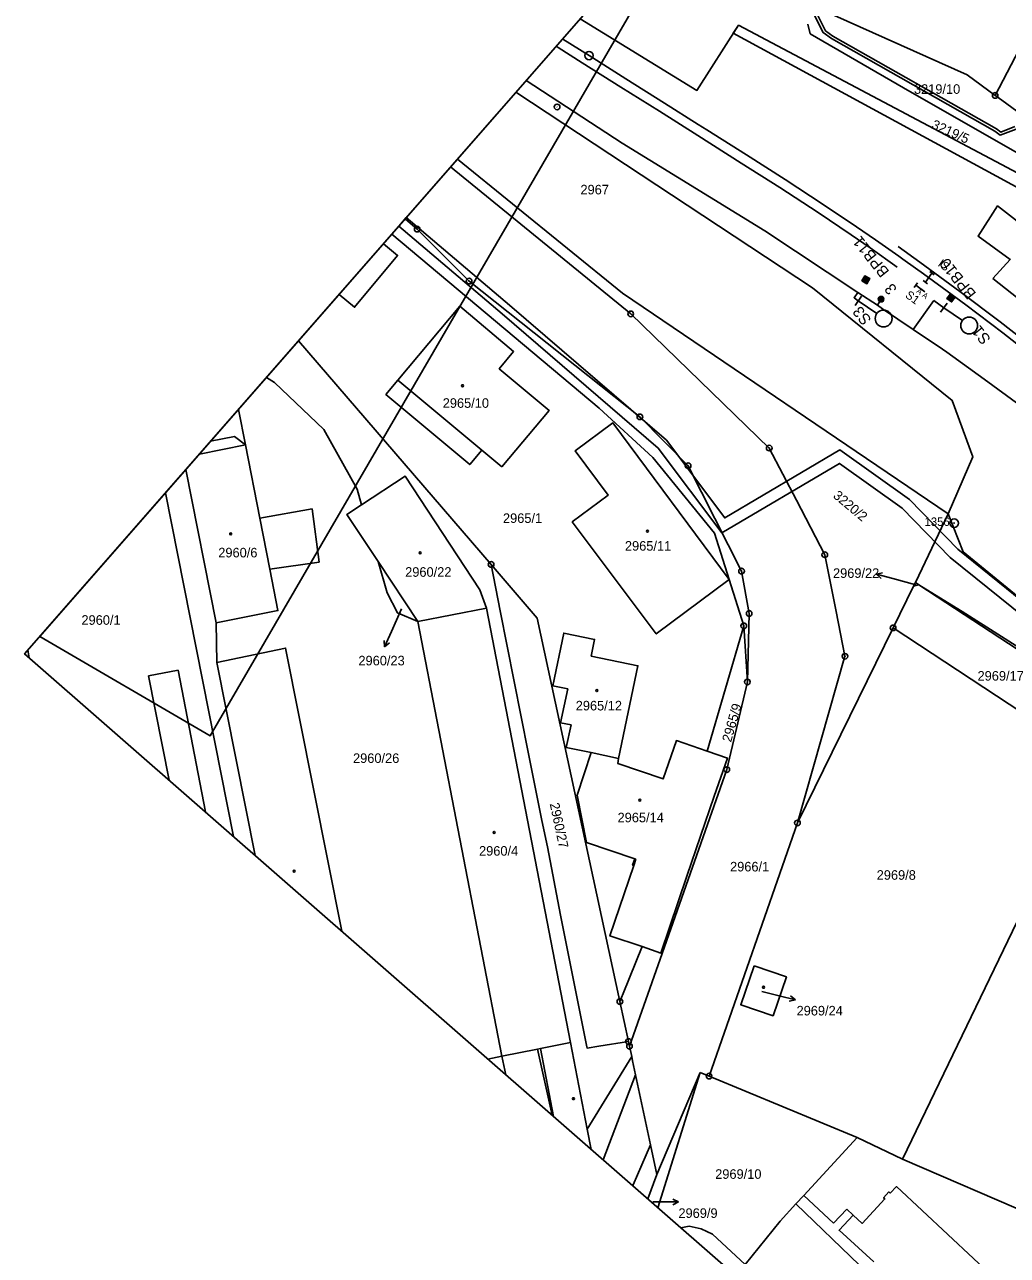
# Model space of a CAD drawing. Extents: x -620475 to -619963, y -1123010 to -1122510.
# Drawn here: x -620474.6 to -620300.1, y -1122840.5 to -1122621.9 of the extents above; entities that cross this region are included whole.
import ezdxf

# ---------------------------------------------------------------- set-up
doc = ezdxf.new("R2010")
doc.units = 0
for name, color, linetype in [('HranDP', 7, 'Continuous'), ('Hranice parcel', 7, 'Continuous'), ('Parcelní čísla', 7, 'Continuous'), ('Pop  PČ popisy', 7, 'Continuous'), ('Rámečky', 7, 'Continuous'), ('Rámečky-tisk', 7, 'Continuous'), ('Vnitřní kresba', 7, 'Continuous'), ('Vrstva 1', 7, 'Continuous'), ('Vrstva 14', 7, 'Continuous'), ('Vrstva 2', 7, 'Continuous'), ('Vrstva 3', 7, 'Continuous'), ('Vrstva 4', 7, 'Continuous'), ('Vrstva 51', 7, 'Continuous'), ('Vrstva 6', 7, 'Continuous'), ('Vrstva 7', 7, 'Continuous'), ('Věcná břemena k části', 7, 'Continuous'), ('Značky bodu BP', 7, 'Continuous'), ('Značky budov', 7, 'Continuous')]:
    doc.layers.add(name, color=color, linetype=linetype)

msp = doc.modelspace()

# ---------------------------------------------------------------- linework, layer by layer
at = {"layer": 'HranDP'}
for points in [[(-620297.09, -1122645.35), (-620318.55, -1122633.1), (-620335.09, -1122623.49), (-620335.54, -1122621.75)], [(-620310.57, -1122708.76), (-620306.2, -1122698.65), (-620309.9, -1122688.62), (-620334.71, -1122668.63), (-620387.37, -1122633.88)], [(-620310.57, -1122708.76), (-620307.94, -1122715.53), (-620278.65, -1122739.48), (-620275.74, -1122741.01)]]:
    msp.add_lwpolyline(points, dxfattribs=at)
at = {"layer": 'Hranice parcel'}
for p, q in [((-620302.25, -1122634.43), (-620294.15, -1122618.83)), ((-620435.41, -1122696.52), (-620436.65, -1122690.22)), ((-620316.42, -1122720.94), (-620310.57, -1122708.76)), ((-620411.83, -1122717.24), (-620404.8, -1122727.88)), ((-620320.37, -1122729), (-620316.74, -1122721.6)), ((-620316.74, -1122721.6), (-620316.42, -1122720.94)), ((-620315.79, -1122721.36), (-620316.74, -1122721.6)), ((-620315.79, -1122721.36), (-620316.42, -1122720.94)), ((-620280.66, -1122744.45), (-620315.79, -1122721.36)), ((-620392.56, -1122725.51), (-620404.8, -1122727.88)), ((-620392.56, -1122725.51), (-620377.65, -1122802.63)), ((-620440.5, -1122735.14), (-620440.62, -1122728.09)), ((-620404.8, -1122727.88), (-620389.89, -1122805.11)), ((-620353.41, -1122750.9), (-620346.9, -1122728.66)), ((-620346.9, -1122728.66), (-620346.26, -1122738.61)), ((-620320.37, -1122729), (-620337.36, -1122763.66)), ((-620284.57, -1122752.56), (-620320.37, -1122729)), ((-620337.36, -1122763.66), (-620328.93, -1122734.05)), ((-620373.99, -1122751.17), (-620369.13, -1122752.19)), ((-620284.57, -1122752.56), (-620318.73, -1122823.4)), ((-620353.06, -1122808.63), (-620337.36, -1122763.66)), ((-620368.9, -1122795.38), (-620367.37, -1122802.49)), ((-620367.19, -1122803.33), (-620367.37, -1122802.49)), ((-620383.51, -1122803.82), (-620389.89, -1122805.11)), ((-620383.51, -1122803.82), (-620383.02, -1122803.72)), ((-620383.02, -1122803.72), (-620377.65, -1122802.63)), ((-620377.65, -1122802.63), (-620374.68, -1122818.03)), ((-620366.79, -1122805.17), (-620367.19, -1122803.33)), ((-620389.89, -1122805.11), (-620392.33, -1122805.6)), ((-620374.68, -1122818.03), (-620366.79, -1122805.17)), ((-620362.33, -1122826.09), (-620354.63, -1122807.98)), ((-620362.14, -1122832), (-620354.63, -1122807.98)), ((-620354.63, -1122807.98), (-620353.06, -1122808.63)), ((-620353.06, -1122808.63), (-620326.76, -1122819.51)), ((-620318.73, -1122823.4), (-620326.76, -1122819.51)), ((-620318.73, -1122823.4), (-620280.92, -1122839.64)), ((-620363.95, -1122830.42), (-620362.33, -1122826.09))]:
    msp.add_line(p, q, dxfattribs=at)
for points in [[(-620296.23, -1122649.3), (-620347.83, -1122621.96), (-620355.23, -1122633.54), (-620375.94, -1122620.82)], [(-620333.59, -1122619.01), (-620307.23, -1122630.79), (-620302.25, -1122634.43)], [(-620297.09, -1122645.35), (-620318.55, -1122633.1), (-620335.09, -1122623.49), (-620335.54, -1122621.75)], [(-620310.57, -1122708.76), (-620306.2, -1122698.65), (-620309.9, -1122688.62), (-620334.71, -1122668.63), (-620387.37, -1122633.88)], [(-620302.25, -1122634.43), (-620301.71, -1122634.83), (-620292.25, -1122641.75)], [(-620342.37, -1122697.07), (-620366.98, -1122673.23), (-620398.96, -1122647.13)], [(-620397.76, -1122645.76), (-620368.46, -1122669.58), (-620310.57, -1122708.76)], [(-620302.66, -1122666.96), (-620267.81, -1122694.49), (-620266.86, -1122693.31), (-620261.82, -1122686.93), (-620261.22, -1122686.17), (-620299.15, -1122656.1), (-620301.83, -1122654.06), (-620305.28, -1122659.46), (-620299.56, -1122663.58), (-620302.66, -1122666.96)], [(-620407.03, -1122656.36), (-620404.9, -1122658.18), (-620395.68, -1122667.41), (-620365.35, -1122691.52), (-620356.78, -1122700.2), (-620347.29, -1122718.92), (-620345.94, -1122726.44), (-620346.26, -1122738.61)], [(-620346.9, -1122728.66), (-620349.5, -1122720.4), (-620352.08, -1122712.18), (-620363.06, -1122698.75), (-620372.55, -1122689.97), (-620409.4, -1122659.07)], [(-620410.89, -1122660.77), (-620408.37, -1122662.86), (-620416.01, -1122672.06), (-620418.76, -1122669.77)], [(-620389.88, -1122700.43), (-620393.43, -1122697.46), (-620395.56, -1122700.01), (-620410.45, -1122687.55), (-620408.32, -1122685), (-620397.34, -1122671.88), (-620387.77, -1122679.92), (-620390.32, -1122682.97), (-620381.44, -1122690.4), (-620389.88, -1122700.43)], [(-620391.77, -1122717.74), (-620425.96, -1122678)], [(-620431.67, -1122684.53), (-620430.21, -1122685.42), (-620421.46, -1122693.76), (-620415.57, -1122704.35), (-620414.76, -1122707.13)], [(-620349.5, -1122720.4), (-620362.45, -1122730.09), (-620377.36, -1122710.19), (-620370.99, -1122705.44), (-620376.85, -1122697.59), (-620370.13, -1122692.59), (-620349.5, -1122720.4)], [(-620443.58, -1122698.14), (-620435.41, -1122696.52)], [(-620440.62, -1122728.09), (-620429.62, -1122725.94), (-620431.07, -1122718.59), (-620432.85, -1122709.54), (-620435.41, -1122696.52)], [(-620328.93, -1122734.05), (-620330.51, -1122726.08), (-620332.51, -1122716.01), (-620337.56, -1122706.31), (-620342.37, -1122697.07)], [(-620440.62, -1122728.09), (-620445.96, -1122700.85)], [(-620414.76, -1122707.13), (-620407.04, -1122702.06), (-620393.75, -1122722.26), (-620392.56, -1122725.51)], [(-620414.76, -1122707.13), (-620417.37, -1122708.84), (-620411.83, -1122717.24)], [(-620310.57, -1122708.76), (-620307.94, -1122715.53), (-620278.65, -1122739.48), (-620275.74, -1122741.01)], [(-620411.83, -1122717.24), (-620410.22, -1122722.77), (-620408.42, -1122726.33), (-620404.8, -1122727.88)], [(-620391.77, -1122717.74), (-620383.57, -1122727.26), (-620368.9, -1122795.38)], [(-620367.37, -1122802.49), (-620372.62, -1122803.29), (-620374.73, -1122803.66), (-620374.83, -1122803.1), (-620379.42, -1122780.06), (-620381.78, -1122767.9), (-620382.73, -1122763.21), (-620385.21, -1122751.08), (-620390.13, -1122725.98), (-620391.77, -1122717.74)], [(-620243.2, -1122764.91), (-620246.23, -1122763.17), (-620280.18, -1122743.84), (-620308.1, -1122726.09), (-620315.79, -1122721.36)], [(-620373.99, -1122751.17), (-620378.41, -1122750.24), (-620377.57, -1122746.24), (-620379.43, -1122745.85), (-620378.17, -1122739.85), (-620380.83, -1122739.29), (-620378.87, -1122729.94), (-620373.38, -1122731.07), (-620373.97, -1122734.01), (-620365.7, -1122735.74), (-620369.13, -1122752.19)], [(-620418.29, -1122782.89), (-620428.27, -1122732.6), (-620440.5, -1122735.14)], [(-620474.07, -1122732.99), (-620473.82, -1122734.31)], [(-620433.66, -1122769.44), (-620440.5, -1122735.14)], [(-620346.26, -1122738.61), (-620349.91, -1122754.18), (-620361.74, -1122787.84), (-620367.19, -1122803.33)], [(-620369.13, -1122752.19), (-620369.27, -1122753.08), (-620361.19, -1122755.84), (-620358.86, -1122749.03), (-620353.41, -1122750.9)], [(-620364.94, -1122785.63), (-620370.66, -1122783.71), (-620366.44, -1122771.24), (-620366.65, -1122771.17), (-620366.25, -1122770.01), (-620374.82, -1122767.12), (-620376.48, -1122758.71), (-620373.99, -1122751.17)], [(-620353.41, -1122750.9), (-620349.8, -1122752.13), (-620352.16, -1122758.92), (-620357, -1122773.13), (-620361.6, -1122786.76), (-620364.94, -1122785.63)], [(-620368.9, -1122795.38), (-620368.33, -1122793.98), (-620364.94, -1122785.63)], [(-620345.02, -1122789.02), (-620339.31, -1122791.01), (-620341.69, -1122797.91), (-620347.42, -1122795.94), (-620345.02, -1122789.02)], [(-620380.95, -1122815.55), (-620383.51, -1122803.82)], [(-620383.02, -1122803.72), (-620380.67, -1122815.79)], [(-620366.1, -1122808.4), (-620366.63, -1122805.92), (-620366.79, -1122805.17)], [(-620371.87, -1122823.49), (-620366.1, -1122808.4)], [(-620366.1, -1122808.4), (-620363.45, -1122820.82), (-620362.33, -1122826.09)], [(-620374.68, -1122818.03), (-620373.98, -1122821.65)], [(-620326.76, -1122819.51), (-620336.22, -1122829.85), (-620337.65, -1122831.34), (-620340.44, -1122834.38), (-620346.62, -1122842.11), (-620352.46, -1122836.69), (-620354.47, -1122835.76), (-620356.61, -1122835.3), (-620358.07, -1122835.57)], [(-620323.82, -1122841.64), (-620329.96, -1122836), (-620327.44, -1122833.35), (-620325.88, -1122834.8), (-620321.83, -1122830.45), (-620322.07, -1122830.23), (-620321.11, -1122829.2), (-620320.88, -1122829.41), (-620319.79, -1122828.24), (-620301.53, -1122845.3)]]:
    msp.add_lwpolyline(points, dxfattribs=at)
at = {"layer": 'Pop  PČ popisy'}
for p, q in [((-620323.34, -1122719.48), (-620322.24, -1122719.26)), ((-620320.44, -1122720.26), (-620323.34, -1122719.48)), ((-620323.34, -1122719.48), (-620322.5, -1122720.23)), ((-620316.31, -1122721.37), (-620320.44, -1122720.26)), ((-620407.69, -1122725.63), (-620409.46, -1122729.64)), ((-620409.46, -1122729.64), (-620410.68, -1122732.38)), ((-620410.68, -1122732.38), (-620410.73, -1122731.26)), ((-620410.68, -1122732.38), (-620409.82, -1122731.67)), ((-620343.66, -1122793.6), (-620340.63, -1122794.37)), ((-620340.63, -1122794.37), (-620337.72, -1122795.1)), ((-620337.72, -1122795.1), (-620338.81, -1122795.34)), ((-620337.72, -1122795.1), (-620338.57, -1122794.37)), ((-620361.5, -1122830.98), (-620363.03, -1122830.98)), ((-620361.5, -1122830.98), (-620358.5, -1122830.98)), ((-620358.5, -1122830.98), (-620359.5, -1122830.48)), ((-620358.5, -1122830.98), (-620359.5, -1122831.48))]:
    msp.add_line(p, q, dxfattribs=at)
at = {"layer": 'Rámečky'}
msp.add_lwpolyline([(-620279.07, -1122510.07), (-620474.61, -1122733.62), (-620158.49, -1123010.14)], dxfattribs=at)
at = {"layer": 'Rámečky-tisk'}
msp.add_line((-620351.12, -1122592.44), (-620471.94, -1122730.56), dxfattribs=at)
for points in [[(-620279.07, -1122510.07), (-620474.61, -1122733.62), (-620158.49, -1123010.14)], [(-620471.94, -1122730.56), (-620441.66, -1122748.16), (-620351.12, -1122592.44)]]:
    msp.add_lwpolyline(points, dxfattribs=at)
at = {"layer": 'Vnitřní kresba'}
for p, q in [((-620393.43, -1122697.46), (-620408.32, -1122685)), ((-620437.36, -1122695.04), (-620441.6, -1122695.87)), ((-620437.36, -1122695.04), (-620435.41, -1122696.52)), ((-620449.62, -1122705.04), (-620437.54, -1122766.05)), ((-620432.85, -1122709.54), (-620423.56, -1122707.88)), ((-620423.56, -1122707.88), (-620422.3, -1122717.35)), ((-620422.3, -1122717.35), (-620431.07, -1122718.59)), ((-620447.35, -1122736.5), (-620452.59, -1122737.55)), ((-620442.49, -1122761.71), (-620447.35, -1122736.5)), ((-620448.97, -1122756.05), (-620452.59, -1122737.55)), ((-620366.44, -1122771.24), (-620366.05, -1122770.08)), ((-620366.25, -1122770.01), (-620366.05, -1122770.08)), ((-620389.89, -1122805.11), (-620389.13, -1122808.4)), ((-620366.52, -1122827.92), (-620363.45, -1122820.82)), ((-620366.59, -1122828.11), (-620366.52, -1122827.92)), ((-620366.52, -1122827.92), (-620366.59, -1122828.11)), ((-620330.98, -1122834.72), (-620336.22, -1122829.85)), ((-620337.65, -1122831.34), (-620326.36, -1122842.19)), ((-620328.61, -1122832.23), (-620330.98, -1122834.72)), ((-620327.44, -1122833.35), (-620328.61, -1122832.23))]:
    msp.add_line(p, q, dxfattribs=at)
at = {"layer": 'Vrstva 1'}
for p, q in [((-620323.17, -1122671.7), (-620326.63, -1122669.41)), ((-620322.52, -1122670.62), (-620323.17, -1122671.7)), ((-620313.16, -1122670.85), (-620316.82, -1122675.99)), ((-620311.36, -1122672.15), (-620313.16, -1122670.85))]:
    msp.add_line(p, q, dxfattribs=at)
for points in [[(-620379.07, -1122624.4), (-620379.01, -1122624.44), (-620374.38, -1122627.36), (-620367.83, -1122631.49), (-620360.99, -1122635.8), (-620354.98, -1122639.59), (-620353.48, -1122640.53), (-620346.44, -1122644.97), (-620339.56, -1122649.37), (-620332.79, -1122653.78), (-620326.85, -1122657.77), (-620323.49, -1122660.07), (-620319.33, -1122663), (-620318.62, -1122663.49), (-620316.38, -1122665.1), (-620314.97, -1122666.12), (-620314.06, -1122666.78), (-620307.46, -1122671.65), (-620300.91, -1122676.61), (-620294.55, -1122681.56)], [(-620326.63, -1122669.41), (-620343.18, -1122658.46), (-620368.5, -1122642.9), (-620385.56, -1122631.81)], [(-620326.57, -1122670.9), (-620327.3, -1122670.38), (-620326.63, -1122669.41)], [(-620316.82, -1122675.99), (-620322.23, -1122672.32), (-620323.17, -1122671.7)], [(-620288.27, -1122699.25), (-620297.82, -1122689.49), (-620304.22, -1122684.86), (-620310.82, -1122680.06), (-620311.61, -1122679.52), (-620316.82, -1122675.99)]]:
    msp.add_lwpolyline(points, dxfattribs=at)
at = {"layer": 'Vrstva 14'}
msp.add_lwpolyline([(-620380.23, -1122625.71), (-620379.87, -1122625.94), (-620375.57, -1122628.64), (-620368.73, -1122632.95), (-620361.89, -1122637.25), (-620355.04, -1122641.55), (-620347.33, -1122646.47), (-620340.48, -1122650.8), (-620333.68, -1122655.25), (-620327.8, -1122659.17), (-620324.47, -1122661.49), (-620319.64, -1122664.92)], dxfattribs=at)
at = {"layer": 'Vrstva 2'}
for p, q in [((-620325.89, -1122667.3), (-620324.54, -1122666.95)), ((-620325.8, -1122667.14), (-620324.7, -1122666.86)), ((-620325.7, -1122666.98), (-620324.86, -1122666.76)), ((-620325.61, -1122666.82), (-620325.02, -1122666.67)), ((-620325.51, -1122666.66), (-620325.18, -1122666.57)), ((-620325.42, -1122666.5), (-620325.34, -1122666.48)), ((-620325.82, -1122667.42), (-620324.55, -1122667.09)), ((-620325.66, -1122667.51), (-620324.64, -1122667.25)), ((-620325.5, -1122667.6), (-620324.74, -1122667.41)), ((-620325.34, -1122667.7), (-620324.83, -1122667.57)), ((-620325.18, -1122667.79), (-620324.92, -1122667.73)), ((-620325.99, -1122670.08), (-620327.14, -1122671.72)), ((-620323.29, -1122673.19), (-620326.57, -1122670.9)), ((-620323.01, -1122670.53), (-620322.12, -1122670.32)), ((-620323.01, -1122670.74), (-620322.04, -1122670.5)), ((-620322.92, -1122670.92), (-620322.03, -1122670.71)), ((-620322.9, -1122670.3), (-620322.33, -1122670.16)), ((-620322.72, -1122671.08), (-620322.14, -1122670.94)), ((-620310.79, -1122671.33), (-620311.93, -1122672.96)), ((-620310.8, -1122670.44), (-620309.42, -1122670.24)), ((-620310.74, -1122670.56), (-620309.44, -1122670.37)), ((-620310.69, -1122670.29), (-620309.57, -1122670.13)), ((-620310.59, -1122670.67), (-620309.55, -1122670.52)), ((-620310.58, -1122670.14), (-620309.72, -1122670.01)), ((-620310.47, -1122669.99), (-620309.87, -1122669.9)), ((-620310.44, -1122670.78), (-620309.66, -1122670.67)), ((-620310.36, -1122669.84), (-620310.02, -1122669.79)), ((-620310.29, -1122670.9), (-620309.78, -1122670.82)), ((-620310.25, -1122669.69), (-620310.16, -1122669.68)), ((-620310.14, -1122671.01), (-620309.89, -1122670.97)), ((-620308.08, -1122674.44), (-620311.36, -1122672.15))]:
    msp.add_line(p, q, dxfattribs=at)
for points in [[(-620325.39, -1122666.45), (-620324.48, -1122666.98), (-620325.02, -1122667.89), (-620325.92, -1122667.35)], [(-620325.39, -1122666.45), (-620324.48, -1122666.98), (-620325.02, -1122667.89), (-620325.92, -1122667.35)], [(-620310.21, -1122669.65), (-620309.37, -1122670.27), (-620310, -1122671.12), (-620310.84, -1122670.49)], [(-620310.21, -1122669.65), (-620309.37, -1122670.27), (-620310, -1122671.12), (-620310.84, -1122670.49)]]:
    msp.add_lwpolyline(points, close=True, dxfattribs=at)
for centre, radius in [((-620322.52, -1122670.62), 0.5), ((-620322.06, -1122674.06), 1.5), ((-620306.86, -1122675.3), 1.5)]:
    msp.add_circle(centre, radius, dxfattribs=at)
at = {"layer": 'Vrstva 3'}
for p, q in [((-620313.47, -1122665.98), (-620314.65, -1122667.59)), ((-620313.87, -1122665.68), (-620313.07, -1122666.27)), ((-620315.06, -1122667.29), (-620314.25, -1122667.88))]:
    msp.add_line(p, q, dxfattribs=at)
at = {"layer": 'Vrstva 4'}
msp.add_lwpolyline([(-620319.33, -1122663), (-620318.62, -1122663.49), (-620316.38, -1122665.1)], dxfattribs=at)
at = {"layer": 'Vrstva 51'}
msp.add_lwpolyline([(-620319.5, -1122661.29), (-620315.63, -1122664.05), (-620308.5, -1122669.28), (-620301.34, -1122674.65), (-620293.26, -1122680.96), (-620288.09, -1122685.04), (-620287.72, -1122684.65), (-620280.59, -1122690.26), (-620273.34, -1122696.07), (-620269.67, -1122699.33)], dxfattribs=at)
at = {"layer": 'Vrstva 6'}
for p, q in [((-620316.04, -1122667.72), (-620316.63, -1122668.53)), ((-620314.74, -1122669.3), (-620316.34, -1122668.13))]:
    msp.add_line(p, q, dxfattribs=at)
at = {"layer": 'Vrstva 7'}
msp.add_line((-620380.09, -1122636.45), (-620380.01, -1122636.5), dxfattribs=at)
for centre, radius in [((-620374.38, -1122627.36), 0.75), ((-620380.05, -1122636.48), 0.5)]:
    msp.add_circle(centre, radius, dxfattribs=at)
at = {"layer": 'Věcná břemena k části'}
msp.add_line((-620406.83, -1122656.13), (-620408.15, -1122657.63), dxfattribs=at)
for points in [[(-620334.39, -1122620.13), (-620332.8, -1122623.28), (-620331.31, -1122624.3), (-620302.28, -1122640.81), (-620301.34, -1122641.49), (-620298.51, -1122640.4)], [(-620298.73, -1122639.94), (-620301.26, -1122640.93), (-620302, -1122640.39), (-620331.05, -1122623.88), (-620332.41, -1122622.94), (-620334.05, -1122619.66)], [(-620408.15, -1122657.63), (-620389.78, -1122673.21), (-620362.07, -1122697.07), (-620350.79, -1122712.11), (-620329.91, -1122699.79), (-620318.75, -1122707.75), (-620310.23, -1122716.49), (-620285.9, -1122736.09), (-620287.87, -1122738.92), (-620280.66, -1122744.45), (-620246.32, -1122763.41), (-620202.66, -1122784.39), (-620201.79, -1122782.59), (-620245.45, -1122761.61), (-620279.7, -1122742.7), (-620285.15, -1122738.52), (-620283.23, -1122735.73), (-620308.89, -1122715.01), (-620317.45, -1122706.23), (-620329.81, -1122697.41), (-620350.27, -1122709.47), (-620360.61, -1122695.69), (-620388.48, -1122671.69), (-620406.83, -1122656.13)]]:
    msp.add_lwpolyline(points, dxfattribs=at)
msp.add_lwpolyline([(-620297.19, -1122651.39), (-620296.23, -1122649.3), (-620347.83, -1122621.96), (-620348.75, -1122623.39)], close=True, dxfattribs=at)
at = {"layer": 'Značky bodu BP'}
for centre, radius in [((-620302.25, -1122634.43), 0.5), ((-620302.25, -1122634.43), 0.0303), ((-620404.9, -1122658.18), 0.5), ((-620404.9, -1122658.18), 0.0303), ((-620395.68, -1122667.41), 0.5), ((-620395.68, -1122667.41), 0.0303), ((-620366.98, -1122673.23), 0.5), ((-620366.98, -1122673.23), 0.0303), ((-620365.35, -1122691.52), 0.5), ((-620365.35, -1122691.52), 0.0303), ((-620342.37, -1122697.07), 0.5), ((-620342.37, -1122697.07), 0.0303), ((-620356.78, -1122700.2), 0.5), ((-620356.78, -1122700.2), 0.0303), ((-620309.54, -1122710.4), 0.75), ((-620309.54, -1122710.4), 0.03), ((-620391.77, -1122717.74), 0.5), ((-620332.51, -1122716.01), 0.5), ((-620332.51, -1122716.01), 0.0303), ((-620391.77, -1122717.74), 0.0303), ((-620347.29, -1122718.92), 0.5), ((-620347.29, -1122718.92), 0.0303), ((-620345.94, -1122726.44), 0.5), ((-620346.9, -1122728.66), 0.5), ((-620345.94, -1122726.44), 0.0303), ((-620346.9, -1122728.66), 0.0303), ((-620320.37, -1122729), 0.5), ((-620320.37, -1122729), 0.0303), ((-620328.93, -1122734.05), 0.5), ((-620328.93, -1122734.05), 0.0303), ((-620346.26, -1122738.61), 0.5), ((-620346.26, -1122738.61), 0.0303), ((-620349.91, -1122754.18), 0.5), ((-620349.91, -1122754.18), 0.0303), ((-620337.36, -1122763.66), 0.5), ((-620337.36, -1122763.66), 0.0303), ((-620368.9, -1122795.38), 0.5), ((-620368.9, -1122795.38), 0.0303), ((-620367.37, -1122802.49), 0.5), ((-620367.37, -1122802.49), 0.0303), ((-620367.19, -1122803.33), 0.5), ((-620367.19, -1122803.33), 0.0303), ((-620353.06, -1122808.63), 0.5), ((-620353.06, -1122808.63), 0.0303)]:
    msp.add_circle(centre, radius, dxfattribs=at)
at = {"layer": 'Značky budov'}
for centre in [(-620396.84, -1122685.99), (-620438.02, -1122712.31), (-620364, -1122711.85), (-620404.38, -1122715.7), (-620372.97, -1122740.15), (-620365.36, -1122759.59), (-620391.23, -1122765.33), (-620426.75, -1122772.22), (-620343.38, -1122792.85), (-620377.15, -1122812.63)]:
    msp.add_circle(centre, 0.175, dxfattribs=at)

# ---------------------------------------------------------------- texts
at = {"layer": 'Parcelní čísla'}
for s, p in [('3219/10', (-620316.67, -1122634.15)), ('2967', (-620375.9, -1122652.01)), ('2965/10', (-620400.36, -1122689.92)), ('2965/1', (-620389.66, -1122710.37)), ('2960/6', (-620440.22, -1122716.49)), ('2965/11', (-620368, -1122715.3)), ('2960/22', (-620407.03, -1122719.93)), ('2969/22', (-620331.05, -1122720.13)), ('2960/1', (-620464.52, -1122728.46)), ('2960/23', (-620415.33, -1122735.67)), ('2969/17', (-620305.38, -1122738.38)), ('2965/12', (-620376.74, -1122743.67)), ('2960/26', (-620416.29, -1122753)), ('2965/14', (-620369.31, -1122763.54)), ('2960/4', (-620393.91, -1122769.47)), ('2966/1', (-620349.33, -1122772.27)), ('2969/8', (-620323.29, -1122773.75)), ('2969/24', (-620337.52, -1122797.85)), ('2969/10', (-620351.97, -1122826.87)), ('2969/9', (-620358.5, -1122833.81))]:
    msp.add_text(s, height=1.7, dxfattribs=at).set_placement(p)
for s, rotation, p in [('3219/5', 336, (-620313.68, -1122640.22)), ('3220/2', 320, (-620331.16, -1122705.75)), ('2965/9', 74, (-620349.16, -1122749.42)), ('2960/27', 282, (-620381.37, -1122760.25))]:
    msp.add_text(s, height=1.7, rotation=rotation, dxfattribs=at).set_placement(p)
at = {"layer": 'Vrstva 3'}
for s, height, rotation, p in [('BPB11', 2, 128.542, (-620320.95, -1122665.72)), ('IS', 1.5, 323.6053, (-620312.55, -1122664.62)), ('BPB10', 2, 128.542, (-620305.53, -1122669.62)), ('3', 2, 128.542, (-620319.59, -1122668.81)), ('S3', 2, 128.542, (-620324.12, -1122674.24)), ('S1', 2, 128.542, (-620302.93, -1122677.68))]:
    msp.add_text(s, height=height, rotation=rotation, dxfattribs=at).set_placement(p)
at = {"layer": 'Vrstva 6'}
for s, height, p in [('S1', 1.5, (-620318.35, -1122670.18)), ('  A A ', 1, (-620316.93, -1122668.93))]:
    msp.add_text(s, height=height, rotation=323.6053, dxfattribs=at).set_placement(p)
at = {"layer": 'Značky bodu BP'}
msp.add_text('1356', height=1.5, dxfattribs=at).set_placement((-620314.79, -1122710.9))

doc.saveas('drawing.dxf')
